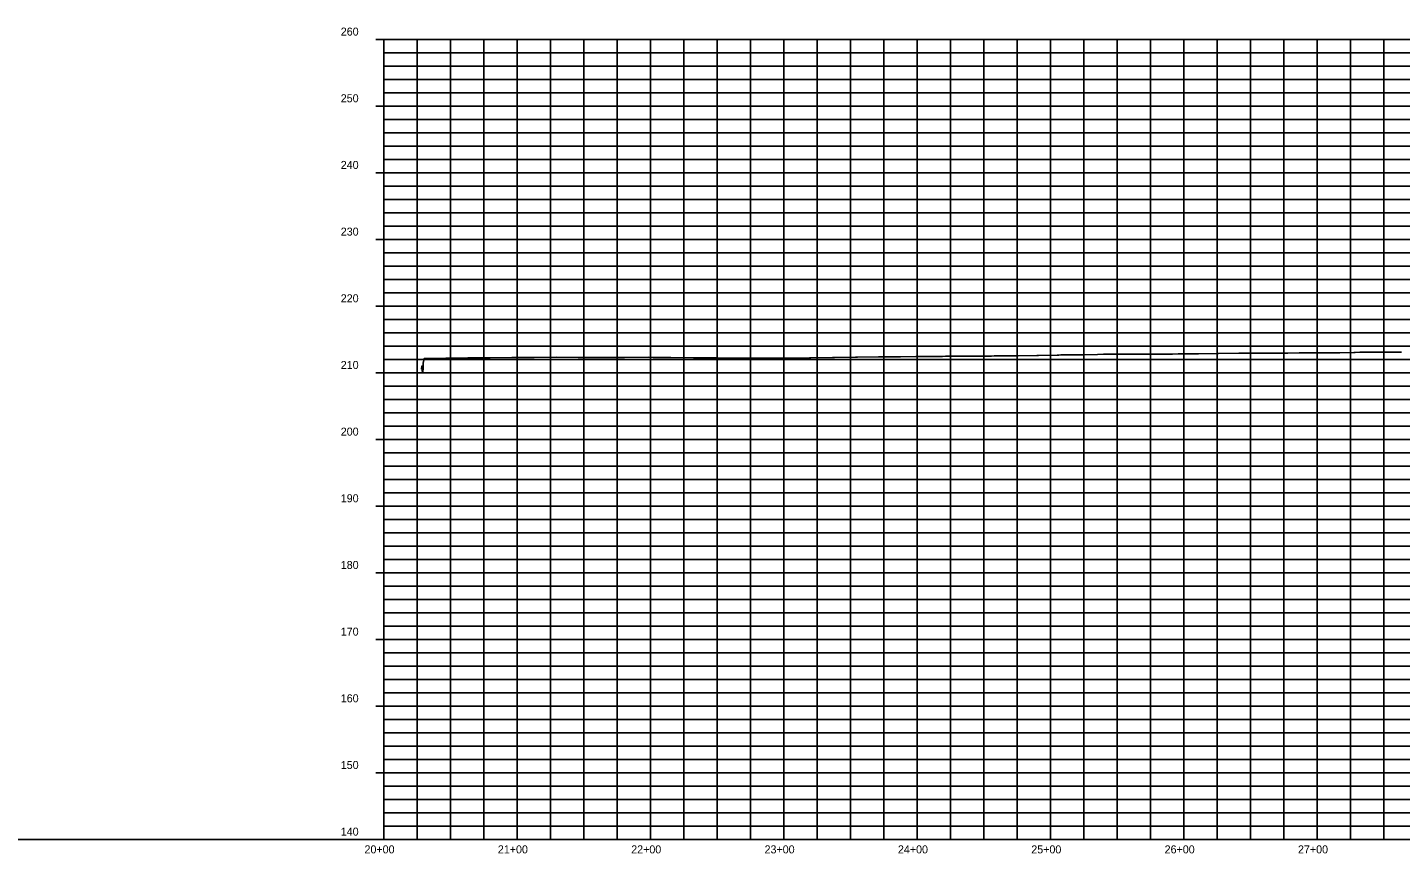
# Model space of a CAD drawing. Extents: x 1732967 to 1742744, y 374025 to 374739.
# Drawn here: x 1739647 to 1740676, y 374119 to 374739 of the extents above; entities that cross this region are included whole.
import ezdxf

# ---------------------------------------------------------------- set-up
doc = ezdxf.new("R2010")
doc.units = 0
for name, color, linetype in [('63', 7, 'Continuous'), ('Level 8', 7, 'Continuous'), ('R_Axis_Annotation', 7, 'Continuous'), ('R_Exist Surface', 7, 'Continuous'), ('R_Grid', 7, 'Continuous'), ('R_Grid Annot', 7, 'Continuous'), ('R_Grid_Minor', 7, 'Continuous')]:
    doc.layers.add(name, color=color, linetype=linetype)

msp = doc.modelspace()

# ---------------------------------------------------------------- linework, layer by layer
at = {"layer": 'Level 8'}
msp.add_line((1738617.1, 374129.6), (1739913.9, 374129.6), dxfattribs=at)
at = {"layer": 'R_Exist Surface'}
msp.add_lwpolyline([(1739942.3, 374482.4), (1739942.6, 374484.9), (1739943.1, 374479.5), (1739943.4, 374482.6), (1739943.4, 374486.1), (1739943.5, 374487), (1739944.2, 374490.4), (1739960.6, 374490.7), (1739976.9, 374490.9), (1739976.9, 374490.9), (1739977, 374490.9), (1739993.5, 374491), (1739993.7, 374491), (1740010, 374491.1), (1740010.5, 374491.1), (1740026.7, 374491.2), (1740043.1, 374491.4), (1740043.3, 374491.4), (1740059.7, 374491.3), (1740060, 374491.3), (1740076.3, 374491.3), (1740076.6, 374491.3), (1740094.3, 374491.3), (1740094.4, 374491.3), (1740112.2, 374491.4), (1740112.3, 374491.4), (1740112.3, 374491.4), (1740115.9, 374491.3), (1740129.2, 374491.2), (1740129.3, 374491.2), (1740146.2, 374491), (1740146.4, 374491), (1740163.2, 374490.9), (1740163.6, 374490.9), (1740180.2, 374490.8), (1740180.8, 374490.8), (1740198, 374490.8), (1740198.8, 374490.8), (1740215.7, 374490.8), (1740216.7, 374490.8), (1740233.1, 374491), (1740234.3, 374491), (1740250.5, 374491.2), (1740251.9, 374491.3), (1740267.8, 374491.5), (1740269.2, 374491.5), (1740285, 374491.7), (1740286.3, 374491.7), (1740299.9, 374491.8), (1740301.4, 374491.8), (1740312.9, 374491.9), (1740314.8, 374491.9), (1740316.9, 374491.9), (1740328, 374492), (1740333, 374492), (1740335.2, 374492.1), (1740343.2, 374492.1), (1740351.2, 374492.2), (1740353.3, 374492.2), (1740358.3, 374492.2), (1740369.6, 374492.3), (1740371.6, 374492.4), (1740373.5, 374492.4), (1740387.9, 374492.5), (1740388.6, 374492.5), (1740389.7, 374492.5), (1740403.7, 374492.8), (1740404.8, 374492.8), (1740418.9, 374493), (1740420.2, 374493), (1740421.7, 374493.1), (1740434, 374493.3), (1740436.9, 374493.3), (1740438.1, 374493.3), (1740449.2, 374493.5), (1740453.6, 374493.6), (1740454.5, 374493.6), (1740464.3, 374493.7), (1740471.2, 374493.7), (1740471.7, 374493.7), (1740479.4, 374493.7), (1740488.8, 374493.7), (1740488.9, 374493.7), (1740488.9, 374493.7), (1740494.6, 374493.8), (1740500.2, 374493.8), (1740505.3, 374493.8), (1740505.3, 374493.8), (1740509.7, 374493.9), (1740521.7, 374493.9), (1740521.9, 374494), (1740524.8, 374494), (1740538.9, 374494.2), (1740539.5, 374494.2), (1740540, 374494.2), (1740555.1, 374494.4), (1740556.2, 374494.4), (1740557.1, 374494.4), (1740570.3, 374494.4), (1740573.6, 374494.5), (1740574.4, 374494.4), (1740585.4, 374494.5), (1740590.9, 374494.5), (1740591.9, 374494.5), (1740600.5, 374494.6), (1740607.8, 374494.6), (1740615.7, 374494.7), (1740623.5, 374494.7), (1740624.6, 374494.8), (1740630.8, 374494.8), (1740641.3, 374495), (1740642.4, 374495), (1740646, 374495.1), (1740659.2, 374495.3), (1740660.3, 374495.3), (1740661.1, 374495.3), (1740676.2, 374495.2), (1740677.1, 374495.2)], dxfattribs=at)
at = {"layer": 'R_Grid'}
for p, q in [((1739913.9, 374129.6), (1739913.9, 374729.6)), ((1739913.9, 374729.6), (1742713.9, 374729.6)), ((1740013.9, 374129.6), (1740013.9, 374729.6)), ((1740113.9, 374129.6), (1740113.9, 374729.6)), ((1740213.9, 374129.6), (1740213.9, 374729.6)), ((1740313.9, 374129.6), (1740313.9, 374729.6)), ((1740413.9, 374129.6), (1740413.9, 374729.6)), ((1740513.9, 374129.6), (1740513.9, 374729.6)), ((1740613.9, 374129.6), (1740613.9, 374729.6)), ((1739913.9, 374679.6), (1742713.9, 374679.6)), ((1739913.9, 374629.6), (1742713.9, 374629.6)), ((1739913.9, 374579.6), (1742713.9, 374579.6)), ((1739913.9, 374529.6), (1742713.9, 374529.6)), ((1739913.9, 374479.6), (1742713.9, 374479.6)), ((1739913.9, 374429.6), (1742713.9, 374429.6)), ((1739913.9, 374379.6), (1742713.9, 374379.6)), ((1739913.9, 374329.6), (1742713.9, 374329.6)), ((1739913.9, 374279.6), (1742713.9, 374279.6)), ((1739913.9, 374229.6), (1742713.9, 374229.6)), ((1739913.9, 374179.6), (1742713.9, 374179.6)), ((1739913.9, 374129.6), (1742713.9, 374129.6))]:
    msp.add_line(p, q, dxfattribs=at)
at = {"layer": 'R_Grid Annot'}
for p, q in [((1739907.9, 374729.6), (1739913.9, 374729.6)), ((1739907.9, 374729.6), (1739913.9, 374729.6)), ((1739913.9, 374719.6), (1739916.9, 374719.6)), ((1739913.9, 374709.6), (1739916.9, 374709.6)), ((1739913.9, 374699.6), (1739916.9, 374699.6)), ((1739913.9, 374689.6), (1739916.9, 374689.6)), ((1739907.9, 374679.6), (1739913.9, 374679.6)), ((1739913.9, 374669.6), (1739916.9, 374669.6)), ((1739913.9, 374659.6), (1739916.9, 374659.6)), ((1739913.9, 374649.6), (1739916.9, 374649.6)), ((1739913.9, 374639.6), (1739916.9, 374639.6)), ((1739907.9, 374629.6), (1739913.9, 374629.6)), ((1739913.9, 374619.6), (1739916.9, 374619.6)), ((1739913.9, 374609.6), (1739916.9, 374609.6)), ((1739913.9, 374599.6), (1739916.9, 374599.6)), ((1739913.9, 374589.6), (1739916.9, 374589.6)), ((1739907.9, 374579.6), (1739913.9, 374579.6)), ((1739913.9, 374569.6), (1739916.9, 374569.6)), ((1739913.9, 374559.6), (1739916.9, 374559.6)), ((1739913.9, 374549.6), (1739916.9, 374549.6)), ((1739913.9, 374539.6), (1739916.9, 374539.6)), ((1739907.9, 374529.6), (1739913.9, 374529.6)), ((1739913.9, 374519.6), (1739916.9, 374519.6)), ((1739913.9, 374509.6), (1739916.9, 374509.6)), ((1739913.9, 374499.6), (1739916.9, 374499.6)), ((1739913.9, 374489.6), (1739916.9, 374489.6)), ((1739907.9, 374479.6), (1739913.9, 374479.6)), ((1739913.9, 374469.6), (1739916.9, 374469.6)), ((1739913.9, 374459.6), (1739916.9, 374459.6)), ((1739913.9, 374449.6), (1739916.9, 374449.6)), ((1739913.9, 374439.6), (1739916.9, 374439.6)), ((1739907.9, 374429.6), (1739913.9, 374429.6)), ((1739913.9, 374419.6), (1739916.9, 374419.6)), ((1739913.9, 374409.6), (1739916.9, 374409.6)), ((1739913.9, 374399.6), (1739916.9, 374399.6)), ((1739913.9, 374389.6), (1739916.9, 374389.6)), ((1739907.9, 374379.6), (1739913.9, 374379.6)), ((1739913.9, 374369.6), (1739916.9, 374369.6)), ((1739913.9, 374359.6), (1739916.9, 374359.6)), ((1739913.9, 374349.6), (1739916.9, 374349.6)), ((1739913.9, 374339.6), (1739916.9, 374339.6)), ((1739907.9, 374329.6), (1739913.9, 374329.6)), ((1739913.9, 374319.6), (1739916.9, 374319.6)), ((1739913.9, 374309.6), (1739916.9, 374309.6)), ((1739913.9, 374299.6), (1739916.9, 374299.6)), ((1739913.9, 374289.6), (1739916.9, 374289.6)), ((1739907.9, 374279.6), (1739913.9, 374279.6)), ((1739913.9, 374269.6), (1739916.9, 374269.6)), ((1739913.9, 374259.6), (1739916.9, 374259.6)), ((1739913.9, 374249.6), (1739916.9, 374249.6)), ((1739913.9, 374239.6), (1739916.9, 374239.6)), ((1739907.9, 374229.6), (1739913.9, 374229.6)), ((1739913.9, 374219.6), (1739916.9, 374219.6)), ((1739913.9, 374209.6), (1739916.9, 374209.6)), ((1739913.9, 374199.6), (1739916.9, 374199.6)), ((1739913.9, 374189.6), (1739916.9, 374189.6)), ((1739907.9, 374179.6), (1739913.9, 374179.6)), ((1739913.9, 374169.6), (1739916.9, 374169.6)), ((1739913.9, 374159.6), (1739916.9, 374159.6)), ((1739913.9, 374149.6), (1739916.9, 374149.6)), ((1739913.9, 374139.6), (1739916.9, 374139.6)), ((1739907.9, 374129.6), (1739913.9, 374129.6))]:
    msp.add_line(p, q, dxfattribs=at)
at = {"layer": 'R_Grid_Minor'}
for p, q in [((1739938.9, 374129.6), (1739938.9, 374729.6)), ((1739963.9, 374129.6), (1739963.9, 374729.6)), ((1739988.9, 374129.6), (1739988.9, 374729.6)), ((1740038.9, 374129.6), (1740038.9, 374729.6)), ((1740063.9, 374129.6), (1740063.9, 374729.6)), ((1740088.9, 374129.6), (1740088.9, 374729.6)), ((1740138.9, 374129.6), (1740138.9, 374729.6)), ((1740163.9, 374129.6), (1740163.9, 374729.6)), ((1740188.9, 374129.6), (1740188.9, 374729.6)), ((1740238.9, 374129.6), (1740238.9, 374729.6)), ((1740263.9, 374129.6), (1740263.9, 374729.6)), ((1740288.9, 374129.6), (1740288.9, 374729.6)), ((1740338.9, 374129.6), (1740338.9, 374729.6)), ((1740363.9, 374129.6), (1740363.9, 374729.6)), ((1740388.9, 374129.6), (1740388.9, 374729.6)), ((1740438.9, 374129.6), (1740438.9, 374729.6)), ((1740463.9, 374129.6), (1740463.9, 374729.6)), ((1740488.9, 374129.6), (1740488.9, 374729.6)), ((1740538.9, 374129.6), (1740538.9, 374729.6)), ((1740563.9, 374129.6), (1740563.9, 374729.6)), ((1740588.9, 374129.6), (1740588.9, 374729.6)), ((1740638.9, 374129.6), (1740638.9, 374729.6)), ((1740663.9, 374129.6), (1740663.9, 374729.6)), ((1739913.9, 374719.6), (1742713.9, 374719.6)), ((1739913.9, 374709.6), (1742713.9, 374709.6)), ((1739913.9, 374699.6), (1742713.9, 374699.6)), ((1739913.9, 374689.6), (1742713.9, 374689.6)), ((1739913.9, 374669.6), (1742713.9, 374669.6)), ((1739913.9, 374659.6), (1742713.9, 374659.6)), ((1739913.9, 374649.6), (1742713.9, 374649.6)), ((1739913.9, 374639.6), (1742713.9, 374639.6)), ((1739913.9, 374619.6), (1742713.9, 374619.6)), ((1739913.9, 374609.6), (1742713.9, 374609.6)), ((1739913.9, 374599.6), (1742713.9, 374599.6)), ((1739913.9, 374589.6), (1742713.9, 374589.6)), ((1739913.9, 374569.6), (1742713.9, 374569.6)), ((1739913.9, 374559.6), (1742713.9, 374559.6)), ((1739913.9, 374549.6), (1742713.9, 374549.6)), ((1739913.9, 374539.6), (1742713.9, 374539.6)), ((1739913.9, 374519.6), (1742713.9, 374519.6)), ((1739913.9, 374509.6), (1742713.9, 374509.6)), ((1739913.9, 374499.6), (1742713.9, 374499.6)), ((1739913.9, 374489.6), (1742713.9, 374489.6)), ((1739913.9, 374469.6), (1742713.9, 374469.6)), ((1739913.9, 374459.6), (1742713.9, 374459.6)), ((1739913.9, 374449.6), (1742713.9, 374449.6)), ((1739913.9, 374439.6), (1742713.9, 374439.6)), ((1739913.9, 374419.6), (1742713.9, 374419.6)), ((1739913.9, 374409.6), (1742713.9, 374409.6)), ((1739913.9, 374399.6), (1742713.9, 374399.6)), ((1739913.9, 374389.6), (1742713.9, 374389.6)), ((1739913.9, 374369.6), (1742713.9, 374369.6)), ((1739913.9, 374359.6), (1742713.9, 374359.6)), ((1739913.9, 374349.6), (1742713.9, 374349.6)), ((1739913.9, 374339.6), (1742713.9, 374339.6)), ((1739913.9, 374319.6), (1742713.9, 374319.6)), ((1739913.9, 374309.6), (1742713.9, 374309.6)), ((1739913.9, 374299.6), (1742713.9, 374299.6)), ((1739913.9, 374289.6), (1742713.9, 374289.6)), ((1739913.9, 374269.6), (1742713.9, 374269.6)), ((1739913.9, 374259.6), (1742713.9, 374259.6)), ((1739913.9, 374249.6), (1742713.9, 374249.6)), ((1739913.9, 374239.6), (1742713.9, 374239.6)), ((1739913.9, 374219.6), (1742713.9, 374219.6)), ((1739913.9, 374209.6), (1742713.9, 374209.6)), ((1739913.9, 374199.6), (1742713.9, 374199.6)), ((1739913.9, 374189.6), (1742713.9, 374189.6)), ((1739913.9, 374169.6), (1742713.9, 374169.6)), ((1739913.9, 374159.6), (1742713.9, 374159.6)), ((1739913.9, 374149.6), (1742713.9, 374149.6)), ((1739913.9, 374139.6), (1742713.9, 374139.6))]:
    msp.add_line(p, q, dxfattribs=at)

# ---------------------------------------------------------------- texts
at = {"layer": '63'}
msp.add_text('-', height=0.0001, dxfattribs=at).set_placement((1739913.9, 374129.6))
at = {"layer": 'R_Axis_Annotation'}
for s, p in [('260', (1739881.7, 374732.6)), ('260', (1739881.7, 374732.6)), ('250', (1739881.7, 374682.6)), ('240', (1739881.7, 374632.6)), ('230', (1739881.7, 374582.6)), ('220', (1739881.7, 374532.6)), ('210', (1739881.7, 374482.6)), ('200', (1739881.7, 374432.6)), ('190', (1739881.7, 374382.6)), ('180', (1739881.7, 374332.6)), ('170', (1739881.7, 374282.6)), ('160', (1739881.7, 374232.6)), ('150', (1739881.7, 374182.6)), ('140', (1739881.7, 374132.6)), ('20+00', (1739899.5, 374119.3)), ('21+00', (1739999.5, 374119.3)), ('22+00', (1740099.5, 374119.3)), ('23+00', (1740199.5, 374119.3)), ('24+00', (1740299.5, 374119.3)), ('25+00', (1740399.5, 374119.3)), ('26+00', (1740499.5, 374119.3)), ('27+00', (1740599.5, 374119.3))]:
    msp.add_text(s, height=6, dxfattribs=at).set_placement(p)

doc.saveas('drawing.dxf')
